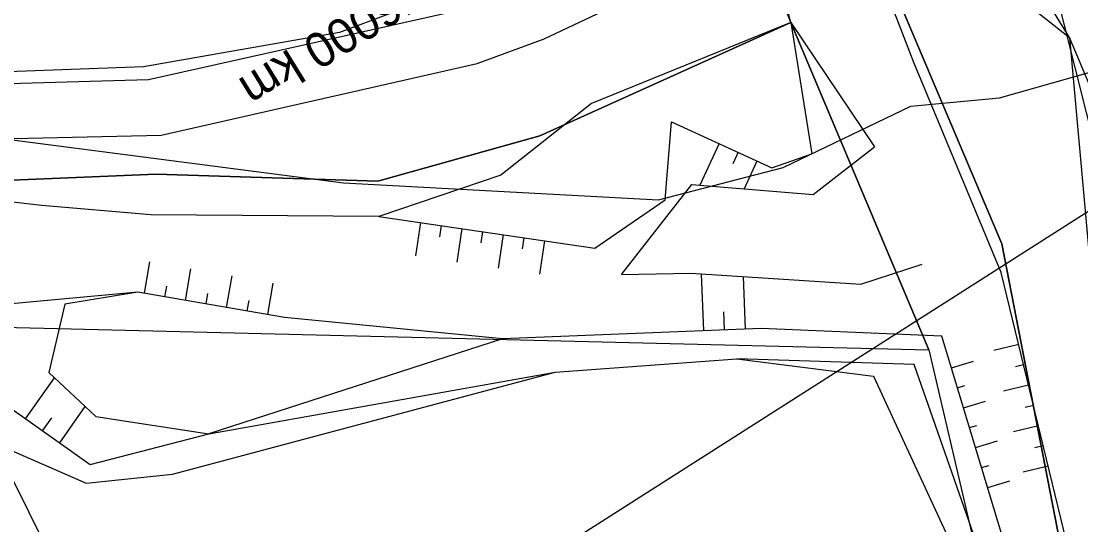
# Model space of a CAD drawing. Extents: x -555887 to -552101, y -1100251 to -1096546.
# Drawn here: x -553892.9 to -553816.7, y -1098359.3 to -1098323 of the extents above; entities that cross this region are included whole.
import ezdxf

# ---------------------------------------------------------------- set-up
doc = ezdxf.new("R2010")
doc.units = 0
for name, color, linetype in [('07_ELEKTRO', 7, 'Continuous'), ('PARCELY_silnice', 7, 'Continuous'), ('PARCELY_VHO', 7, 'Continuous'), ('POLYGONY_SITUACE_PF_POPISY', 7, 'Continuous'), ('vrstevnice', 7, 'Continuous'), ('ZSST', 7, 'Continuous'), ('zájem', 7, 'Continuous')]:
    doc.layers.add(name, color=color, linetype=linetype)

msp = doc.modelspace()

# ---------------------------------------------------------------- linework, layer by layer
at = {"layer": '07_ELEKTRO'}
msp.add_lwpolyline([(-553982.61, -1098443.29), (-553898.74, -1098389.37), (-553814.74, -1098335.79), (-553822.57, -1098304.65)], dxfattribs=at)
at = {"layer": 'PARCELY_silnice'}
msp.add_lwpolyline([(-553954.49, -1098334.56), (-553949.24, -1098332.4), (-553935.89, -1098333.43), (-553913.06, -1098335.28), (-553883.16, -1098334.04), (-553867.22, -1098334.53), (-553855.57, -1098331.27), (-553837.55, -1098323.13), (-553842.59, -1098309.95), (-553846.87, -1098312.9), (-553850.11, -1098315.12), (-553858.85, -1098319.65), (-553869.99, -1098323.86), (-553884.06, -1098326.31), (-553912.66, -1098327.37), (-553935.34, -1098326.53), (-553947.54, -1098323.63), (-553951.31, -1098319.23)], close=True, dxfattribs=at)
at = {"layer": 'PARCELY_VHO'}
msp.add_lwpolyline([(-554187.71, -1098013.33), (-554186.2, -1098028.28), (-554148.41, -1098314.52), (-553977.83, -1098347.65), (-553971.09, -1098348.95), (-553957.61, -1098351.63), (-553953.24, -1098348.19), (-553949.93, -1098338.53), (-553911.81, -1098344.6), (-553827.63, -1098346.66), (-553837.55, -1098323.13), (-553855.57, -1098331.27), (-553867.22, -1098334.53), (-553883.16, -1098334.04), (-553913.06, -1098335.28), (-553935.89, -1098333.43), (-553949.24, -1098332.4), (-553954.49, -1098334.56), (-553956.79, -1098343.64), (-553969.49, -1098341.12), (-553975.92, -1098339.86), (-554126.54, -1098310.27), (-554135.62, -1098304.48), (-554178.28, -1098027.18)], close=True, dxfattribs=at)
for points in [[(-553910.789, -1098134.707), (-553870.98, -1098223.96), (-553858.61, -1098264.81), (-553842.59, -1098309.95), (-553837.55, -1098323.13), (-553827.63, -1098346.66), (-553824.1, -1098361.75), (-553822.88, -1098366.94), (-553824.58, -1098517.22)], [(-553819.71, -1098517.47), (-553816.99, -1098366.76), (-553822.39, -1098339.05), (-553834.84, -1098309.6), (-553837.04, -1098305.33), (-553848.93, -1098273.99), (-553857.57, -1098247.87), (-553865.26, -1098222.5), (-553872.03, -1098204), (-553873.38, -1098200.91), (-553884.8, -1098171.23)]]:
    msp.add_lwpolyline(points, dxfattribs=at)
at = {"layer": 'vrstevnice'}
for points in [[(-553944.364, -1098326.711), (-553917.432, -1098329.034), (-553893.316, -1098331.601), (-553869.689, -1098334.657), (-553847.042, -1098335.879), (-553838.105, -1098333.557), (-553828.924, -1098329.156), (-553822.558, -1098328.545), (-553813.499, -1098325.978), (-553806.072, -1098317.223), (-553786.005, -1098302.458), (-553764.881, -1098293.23)], [(-553854.85, -1098465.324), (-553858.866, -1098450.868), (-553860.481, -1098440.705), (-553860.599, -1098432.337), (-553861.661, -1098422.791), (-553864.021, -1098406.292), (-553872.755, -1098389.675), (-553884.912, -1098373.293), (-553896.036, -1098350.812), (-553902.619, -1098348.347), (-553915.963, -1098346.269), (-553935.795, -1098343.458)]]:
    msp.add_lwpolyline(points, dxfattribs=at)
at = {"layer": 'ZSST'}
for p, q in [((-553837.55, -1098323.13), (-553839.7, -1098314.59)), ((-553837.55, -1098323.13), (-553836.03, -1098332.58)), ((-553837.55, -1098323.13), (-553831.52, -1098332.08)), ((-553828.7, -1098326), (-553828.7, -1098326)), ((-553842.703, -1098331.839), (-553844.079, -1098334.837)), ((-553841.34, -1098332.465), (-553841.722, -1098333.298)), ((-553839.976, -1098333.09), (-553840.897, -1098335.096)), ((-553864.161, -1098337.512), (-553864.516, -1098339.922)), ((-553862.677, -1098337.731), (-553862.795, -1098338.533)), ((-553861.193, -1098337.949), (-553861.548, -1098340.359)), ((-553859.709, -1098338.168), (-553859.827, -1098338.971)), ((-553858.225, -1098338.387), (-553858.58, -1098340.797)), ((-553856.741, -1098338.605), (-553856.859, -1098339.408)), ((-553855.257, -1098338.824), (-553855.612, -1098341.234)), ((-553884.001, -1098342.601), (-553883.609, -1098340.333)), ((-553881.045, -1098343.112), (-553880.653, -1098340.844)), ((-553878.089, -1098343.623), (-553877.697, -1098341.355)), ((-553843.806, -1098345.302), (-553843.967, -1098341.199)), ((-553840.808, -1098345.185), (-553840.957, -1098341.394)), ((-553882.523, -1098342.856), (-553882.393, -1098342.101)), ((-553875.133, -1098344.134), (-553874.741, -1098341.865)), ((-553879.567, -1098343.367), (-553879.437, -1098342.612)), ((-553876.611, -1098343.878), (-553876.481, -1098343.123)), ((-553842.307, -1098345.244), (-553842.359, -1098343.929)), ((-553821.166, -1098346.295), (-553822.956, -1098346.729)), ((-553854.47, -1098348.27), (-553841.43, -1098347.33)), ((-553826.001, -1098347.96), (-553824.417, -1098347.481)), ((-553820.813, -1098347.753), (-553821.409, -1098347.898)), ((-553892.537, -1098351.624), (-553890.455, -1098348.681)), ((-553825.567, -1098349.396), (-553825.04, -1098349.236)), ((-553820.461, -1098349.211), (-553822.251, -1098349.644)), ((-553890.087, -1098353.356), (-553888.248, -1098350.756)), ((-553825.133, -1098350.832), (-553823.549, -1098350.353)), ((-553820.108, -1098350.669), (-553820.704, -1098350.814)), ((-553891.312, -1098352.49), (-553890.659, -1098351.567)), ((-553824.7, -1098352.267), (-553824.172, -1098352.108)), ((-553819.755, -1098352.127), (-553821.546, -1098352.56)), ((-553824.266, -1098353.703), (-553822.682, -1098353.225)), ((-553819.403, -1098353.585), (-553819.999, -1098353.729)), ((-553823.832, -1098355.139), (-553823.304, -1098354.98)), ((-553819.05, -1098355.043), (-553820.841, -1098355.476)), ((-553823.398, -1098356.575), (-553821.814, -1098356.096))]:
    msp.add_line(p, q, dxfattribs=at)
for points in [[(-553883.71, -1098327.25), (-553914.68, -1098328.15), (-553935.1, -1098327.52), (-553946.22, -1098325.88), (-553949.72, -1098323.72), (-553953.54, -1098319.18), (-553954.42, -1098315.73), (-553953.71, -1098303.24), (-553954.34, -1098287.84), (-553957.61, -1098261.59)], [(-553982.61, -1098443.29), (-553898.74, -1098389.37), (-553814.74, -1098335.79), (-553822.57, -1098304.65)], [(-553813.28, -1098334.26), (-553817.51, -1098324.21), (-553825.63, -1098311), (-553830.55, -1098307.81), (-553833.82, -1098307.53)], [(-553889.35, -1098745.65), (-553882.93, -1098723.13), (-553875.04, -1098698.54), (-553869.21, -1098680.04), (-553864.88, -1098666.8), (-553856.74, -1098642.76), (-553849.22, -1098619.35), (-553841.56, -1098593.48), (-553832.4, -1098566.45), (-553824.87, -1098540.95), (-553819.91, -1098526.76), (-553817.36, -1098516.81), (-553817.35, -1098516.78), (-553817.25, -1098499.54), (-553817.67, -1098480.13), (-553816.77, -1098462.81), (-553816.62, -1098441.06), (-553816.2, -1098418.53), (-553814.67, -1098393.91), (-553817.77, -1098360.56), (-553817.74, -1098360.46), (-553822.42, -1098341.11), (-553828.7, -1098326), (-553834.9, -1098309.92)], [(-553842.98, -1098312.03), (-553849.1, -1098316.62), (-553856.83, -1098320.45), (-553861.29, -1098322.25), (-553883.71, -1098327.25)], [(-553882.8, -1098331.23), (-553860.08, -1098326.08), (-553855.26, -1098324.31), (-553846.89, -1098320.32), (-553840.71, -1098315.17)], [(-553828.41, -1098315.58), (-553817.51, -1098324.21), (-553816.16, -1098339.34)], [(-553837.55, -1098323.13), (-553851.86, -1098328.95), (-553858.38, -1098334.1), (-553867.16, -1098337.07), (-553883.54, -1098336.95)], [(-553960.59, -1098344.24), (-553957.5, -1098334.46), (-553956.04, -1098332.65), (-553953.76, -1098331.03), (-553950.84, -1098329.95), (-553947.35, -1098329.98), (-553935.49, -1098331.39), (-553914.72, -1098331.94), (-553882.8, -1098331.23)], [(-553867.16, -1098337.07), (-553851.62, -1098339.36), (-553846.57, -1098335.89), (-553846.12, -1098330.27), (-553838.91, -1098333.58), (-553836.03, -1098332.58)], [(-553849.71, -1098341.25), (-553844.66, -1098334.79), (-553835.94, -1098335.5), (-553831.52, -1098332.08)], [(-553883.54, -1098336.95), (-553891.38, -1098336.3), (-553903.59, -1098334.9), (-553906.16, -1098343.41), (-553894.07, -1098350.54), (-553887.89, -1098354.91), (-553879.36, -1098352.71), (-553854.47, -1098348.27)], [(-553948.1, -1098341.33), (-553945.61, -1098340.58), (-553939.98, -1098340.36), (-553922.17, -1098343.38), (-553910.39, -1098346.11), (-553901.19, -1098350.57), (-553888.19, -1098356.26), (-553881.99, -1098355.61), (-553854.47, -1098348.27)], [(-553849.71, -1098341.25), (-553844.73, -1098341.15), (-553832.52, -1098341.94), (-553828.11, -1098340.5)], [(-553858.26, -1098345.87), (-553873.94, -1098344.34), (-553884.47, -1098342.52), (-553899.53, -1098343.91)], [(-553884.47, -1098342.52), (-553889.71, -1098343.39), (-553890.86, -1098348.3), (-553887.5, -1098351.46), (-553879.36, -1098352.71)], [(-553830.41, -1098541.86), (-553822.95, -1098514.94), (-553822.09, -1098496.12), (-553821.81, -1098469.45), (-553821.51, -1098428.32), (-553821.93, -1098400.58), (-553820.84, -1098377.42), (-553822.33, -1098360.11), (-553826.69, -1098345.68), (-553839.67, -1098345.14), (-553858.26, -1098345.87), (-553879.36, -1098352.71)], [(-553841.43, -1098347.33), (-553831.61, -1098348.56), (-553826.26, -1098360.13), (-553825.16, -1098379.84), (-553825.05, -1098400.18), (-553825.92, -1098428.25), (-553824.92, -1098469.62), (-553825.52, -1098494.83), (-553827.13, -1098516.39), (-553833.59, -1098542.21), (-553845.61, -1098581.68), (-553856.03, -1098615.65), (-553866.3, -1098644.33), (-553873.97, -1098669.17), (-553888.31, -1098712.5), (-553896.32, -1098735.34)], [(-553895.65, -1098744.45), (-553894.22, -1098735.87), (-553885.5, -1098713.24), (-553884.3, -1098704.98), (-553878.65, -1098690.58), (-553872.62, -1098670.76), (-553863.14, -1098645.17), (-553854.12, -1098617.37), (-553842.45, -1098580.09), (-553830.41, -1098541.86), (-553825.12, -1098516.11), (-553823.29, -1098496.4), (-553822.97, -1098469.34), (-553823.13, -1098428.02), (-553823.34, -1098400.78), (-553822.41, -1098378.86), (-553824.25, -1098360.4), (-553828.68, -1098347.72), (-553841.43, -1098347.33)]]:
    msp.add_lwpolyline(points, dxfattribs=at)
at = {"layer": 'zájem'}
for points in [[(-553884.8, -1098171.23), (-553873.38, -1098200.91), (-553872.03, -1098204), (-553865.26, -1098222.5), (-553857.57, -1098247.87), (-553848.93, -1098273.99), (-553837.04, -1098305.33), (-553834.84, -1098309.6), (-553822.39, -1098339.05), (-553816.99, -1098366.76), (-553819.71, -1098517.47)], [(-553819.71, -1098517.47), (-553816.99, -1098366.76), (-553822.39, -1098339.05), (-553834.84, -1098309.6), (-553832.93, -1098306.52), (-553813.65, -1098304.59), (-553811.08, -1098291.9), (-553801.93, -1098280.68), (-553796.19, -1098265.28), (-553793.5, -1098257.9), (-553779.33, -1098244.73), (-553771.72, -1098243.29), (-553770.09, -1098245.93), (-553765.12, -1098244.88), (-553758.21, -1098235.89), (-553761.18, -1098231.7), (-553762.77, -1098213.9), (-553756.6, -1098212.95)]]:
    msp.add_lwpolyline(points, dxfattribs=at)

# ---------------------------------------------------------------- texts
at = {"layer": 'POLYGONY_SITUACE_PF_POPISY'}
msp.add_text('0.76000 km', height=2.5, rotation=211.67586, dxfattribs=at).set_placement((-553862.522, -1098318.133))

doc.saveas('drawing.dxf')
